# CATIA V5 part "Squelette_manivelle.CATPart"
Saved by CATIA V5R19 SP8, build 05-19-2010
Part number: Squelette manivelle
Publications: "Droite.1", "Droite.2", "Plan.1", "Plan.2"
Bounding box of the stored display mesh (mm): x -11 to 11, y 0 to 14, z 0 to 0
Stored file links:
  C:\Users\ThinkMotion\Desktop\EU_thinkMotion\iao\IAO_MMS_Groupe3\ecartoux\projet_IAO_ecartoux\projet_IAO_ecartoux\griffe_d'une_camera_ecartoux\Squelette_manivelle.CATPart
  C:\Users\ThinkMotion\Desktop\EU_thinkMotion\iao\IAO_MMS_Groupe3\ecartoux\projet_IAO_ecartoux\projet_IAO_ecartoux\griffe_d'une_camera_ecartoux\Squelette.CATProduct
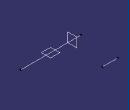
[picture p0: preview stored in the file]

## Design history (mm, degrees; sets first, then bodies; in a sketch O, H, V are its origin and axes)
Set1
  Point1 to Point3: linked copy from another document
  Plane1: linked copy from another document
  Plane2: linked copy from another document
Set2 "Set géométrique"
  Line1: type PtPt, FirstPoint Point1, SecondPoint Point2, Start 11, End 3
  Line2: type PtDir, RefPoint Point3, Direction Plane1, Start 3, End -2.5
  Plane3 "Plan.1": type OffsetPt, RefPlane Plane1, RefPoint Point2
  Plane4 "Plan.2": type Offset, RefPlane Plane2, Offset 0
Body1 (main body)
